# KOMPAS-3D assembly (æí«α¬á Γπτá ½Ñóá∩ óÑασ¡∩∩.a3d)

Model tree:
1. Ломаная:1
2. Перпендикулярная плоскость:1
3. Эскиз:1
4. Кинематическая операция:1
     Толщина стенки 1 = 1; Толщина стенки 2 = 1
5. Ломаная:2
6. Перпендикулярная плоскость:3
7. Эскиз:2
8. Кинематическая операция:3
     Толщина стенки 1 = 1; Толщина стенки 2 = 1

Referenced files in D:\МОДЕЛЬ ТАНКА Т90\ДЕТАЛИ\БАШНЯ\башня сварная\: крепление туча левая верхняя.m3d, туча.m3d
Referenced files in D:\МОДЕЛЬ ТАНКА Т90\СБОРКИ\сборка фара правая\: фара правая.m3d
Referenced files in D:\МОДЕЛЬ ТАНКА Т90\ДЕТАЛИ\ОБЩИЕ ДЕТАЛИ\: болт м1.m3d
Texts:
  Сборка туча левая верхняя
